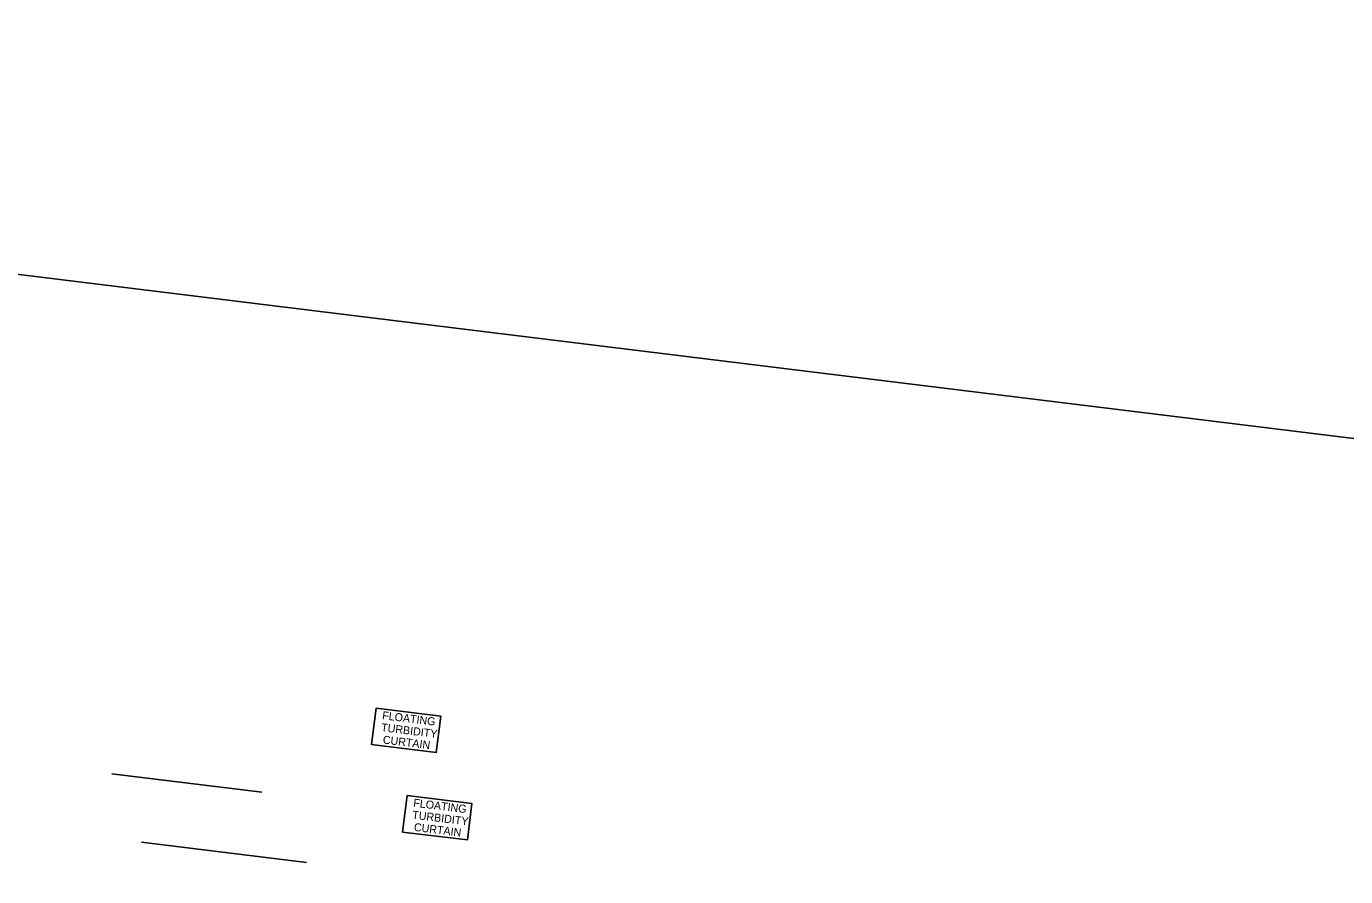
# Model space of a CAD drawing. Extents: x 2470000 to 2520000, y 340000 to 380000.
# Drawn here: x 2482787 to 2483776, y 374481 to 375119 of the extents above; entities that cross this region are included whole.
import ezdxf

# ---------------------------------------------------------------- set-up
doc = ezdxf.new("R2010")
doc.units = 0
for name, color, linetype in [('Floating Turbidity Curtain Both', 7, 'Continuous'), ('Floating Turbidity Curtain CG', 7, 'Continuous'), ('Floating Turbidity Curtain Note Both CELL', 7, 'Continuous'), ('Floating Turbidity Curtain Note CG CELL', 7, 'Continuous'), ('Scratch_Level_5', 7, 'Continuous')]:
    doc.layers.add(name, color=color, linetype=linetype)

msp = doc.modelspace()

# ---------------------------------------------------------------- linework, layer by layer
at = {"layer": 'Floating Turbidity Curtain Both'}
msp.add_line((2482873.26, 374507.02), (2482996.77, 374491.83), dxfattribs=at)
at = {"layer": 'Floating Turbidity Curtain CG'}
msp.add_line((2482851.05, 374558.19), (2482963.34, 374544.39), dxfattribs=at)
at = {"layer": 'Floating Turbidity Curtain Note Both CELL'}
msp.add_lwpolyline([(2483072.28, 374541.92), (2483120.8, 374535.93), (2483117.43, 374508.63), (2483068.91, 374514.61)], close=True, dxfattribs=at)
at = {"layer": 'Floating Turbidity Curtain Note CG CELL'}
msp.add_lwpolyline([(2483048.99, 374607.48), (2483097.51, 374601.49), (2483094.14, 374574.18), (2483045.62, 374580.16)], close=True, dxfattribs=at)
at = {"layer": 'Scratch_Level_5'}
msp.add_lwpolyline([(2481268.48, 375118.62), (2484221.21, 374755.66), (2483894.27, 372095.99), (2480941.54, 372458.95)], close=True, dxfattribs=at)

# ---------------------------------------------------------------- texts
at = {"layer": 'Floating Turbidity Curtain Note Both CELL'}
for s, p in [('FLOATING', (2483076.63, 374533.67)), ('TURBIDITY', (2483075.83, 374524.7)), ('CURTAIN', (2483077.1, 374515.48))]:
    msp.add_text(s, height=6, rotation=352.99213, dxfattribs=at).set_placement(p)
at = {"layer": 'Floating Turbidity Curtain Note CG CELL'}
for s, p in [('FLOATING', (2483053.34, 374599.22)), ('TURBIDITY', (2483052.54, 374590.25)), ('CURTAIN', (2483053.81, 374581.03))]:
    msp.add_text(s, height=6, rotation=352.99213, dxfattribs=at).set_placement(p)

doc.saveas('drawing.dxf')
